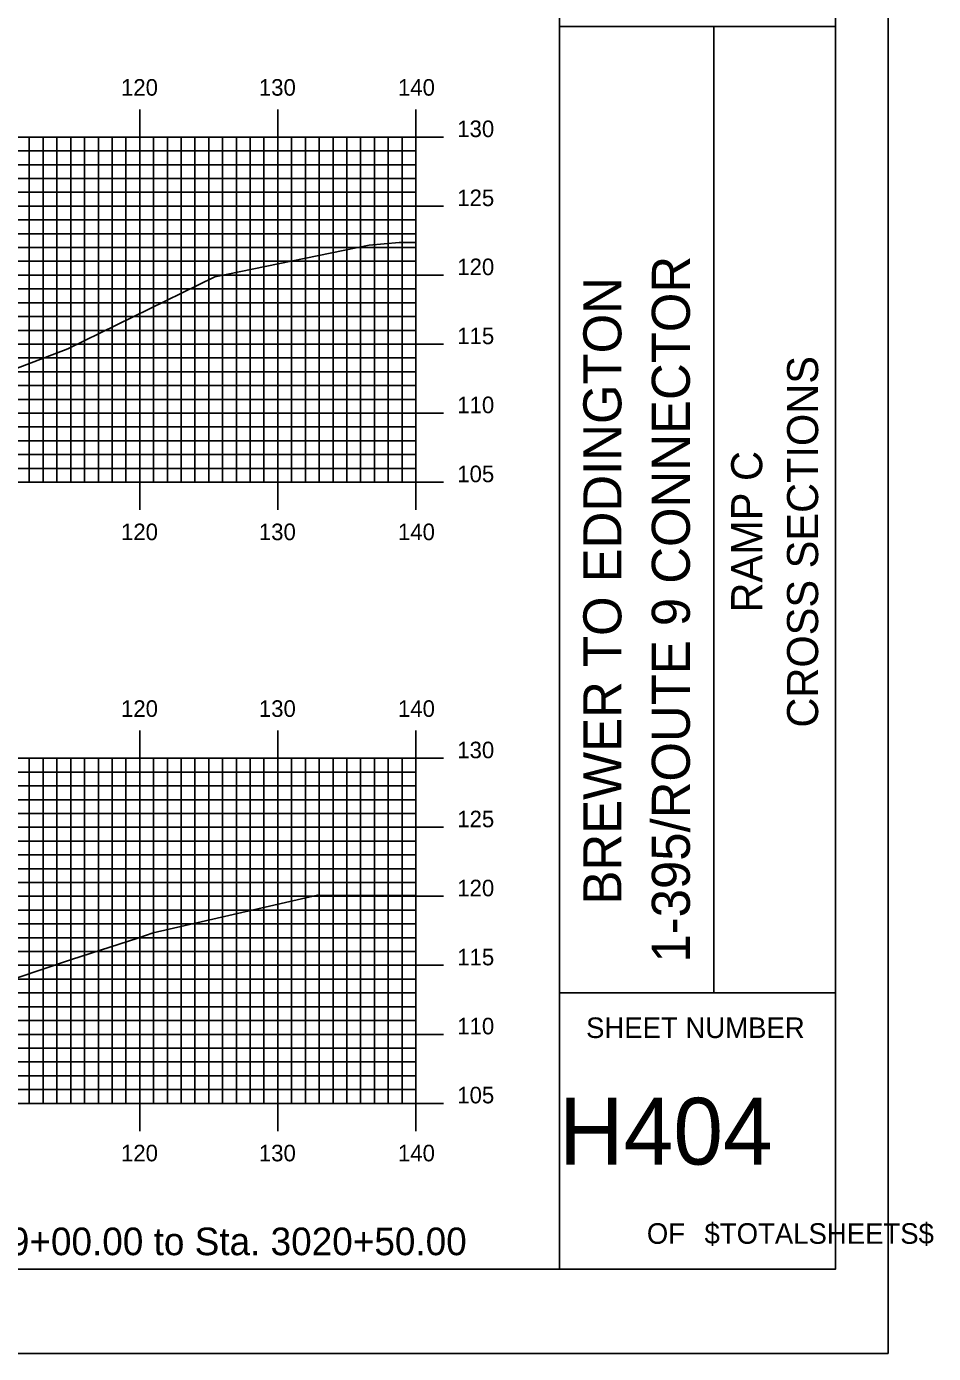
# Model space of a CAD drawing. Extents: x 1685979 to 1686323, y 461260 to 461480.
# Drawn here: x 1686257.1 to 1686322.8, y 461260 to 461356.1 of the extents above; entities that cross this region are included whole.
import ezdxf

# ---------------------------------------------------------------- set-up
doc = ezdxf.new("R2010")
doc.units = 0
for name, color, linetype in [('BORDER', 7, 'Continuous'), ('H_V ANNOTATION', 7, 'Continuous'), ('MAJOR', 7, 'Continuous'), ('MINOR', 7, 'Continuous'), ('PLOT BOUNDARY', 7, 'Continuous'), ('S_Roadway_Centerline', 7, 'Continuous')]:
    doc.layers.add(name, color=color, linetype=linetype)

msp = doc.modelspace()

# ---------------------------------------------------------------- linework, layer by layer
at = {"layer": 'BORDER'}
for p, q in [((1686295.656, 461266.072), (1686295.656, 461476.072)), ((1686295.656, 461356.078), (1686315.656, 461356.078)), ((1686306.838, 461286.078), (1686306.838, 461356.078)), ((1686295.656, 461286.078), (1686315.656, 461286.078))]:
    msp.add_line(p, q, dxfattribs=at)
msp.add_lwpolyline([(1685995.656, 461266.072), (1686315.656, 461266.072), (1686315.656, 461476.072), (1685995.656, 461476.072)], close=True, dxfattribs=at)
at = {"layer": 'MAJOR'}
for p, q in [((1686265.256, 461350.076), (1686265.256, 461348.072)), ((1686275.256, 461350.076), (1686275.256, 461348.072)), ((1686285.256, 461350.076), (1686285.256, 461348.072)), ((1686005.256, 461348.072), (1686285.256, 461348.072)), ((1686005.256, 461348.072), (1686285.256, 461348.072)), ((1686265.256, 461323.072), (1686265.256, 461348.072)), ((1686275.256, 461323.072), (1686275.256, 461348.072)), ((1686287.26, 461348.072), (1686283.252, 461348.072)), ((1686285.256, 461323.072), (1686285.256, 461348.072)), ((1686285.256, 461323.072), (1686285.256, 461348.072)), ((1686005.256, 461343.072), (1686285.256, 461343.072)), ((1686287.26, 461343.072), (1686283.252, 461343.072)), ((1686005.256, 461338.072), (1686285.256, 461338.072)), ((1686287.26, 461338.072), (1686283.252, 461338.072)), ((1686005.256, 461333.072), (1686285.256, 461333.072)), ((1686287.26, 461333.072), (1686283.252, 461333.072)), ((1686005.256, 461328.072), (1686285.256, 461328.072)), ((1686287.26, 461328.072), (1686283.252, 461328.072)), ((1686005.256, 461323.072), (1686285.256, 461323.072)), ((1686005.256, 461323.072), (1686285.256, 461323.072)), ((1686265.256, 461321.068), (1686265.256, 461323.072)), ((1686275.256, 461321.068), (1686275.256, 461323.072)), ((1686287.26, 461323.072), (1686283.252, 461323.072)), ((1686285.256, 461321.068), (1686285.256, 461323.072)), ((1686265.256, 461305.076), (1686265.256, 461303.072)), ((1686275.256, 461305.076), (1686275.256, 461303.072)), ((1686285.256, 461305.076), (1686285.256, 461303.072)), ((1686005.256, 461303.072), (1686285.256, 461303.072)), ((1686005.256, 461303.072), (1686285.256, 461303.072)), ((1686265.256, 461278.072), (1686265.256, 461303.072)), ((1686275.256, 461278.072), (1686275.256, 461303.072)), ((1686287.26, 461303.072), (1686283.252, 461303.072)), ((1686285.256, 461278.072), (1686285.256, 461303.072)), ((1686285.256, 461278.072), (1686285.256, 461303.072)), ((1686005.256, 461298.072), (1686285.256, 461298.072)), ((1686287.26, 461298.072), (1686283.252, 461298.072)), ((1686005.256, 461293.072), (1686285.256, 461293.072)), ((1686287.26, 461293.072), (1686283.252, 461293.072)), ((1686005.256, 461288.072), (1686285.256, 461288.072)), ((1686287.26, 461288.072), (1686283.252, 461288.072)), ((1686005.256, 461283.072), (1686285.256, 461283.072)), ((1686287.26, 461283.072), (1686283.252, 461283.072)), ((1686005.256, 461278.072), (1686285.256, 461278.072)), ((1686005.256, 461278.072), (1686285.256, 461278.072)), ((1686265.256, 461276.068), (1686265.256, 461278.072)), ((1686275.256, 461276.068), (1686275.256, 461278.072)), ((1686287.26, 461278.072), (1686283.252, 461278.072)), ((1686285.256, 461276.068), (1686285.256, 461278.072))]:
    msp.add_line(p, q, dxfattribs=at)
at = {"layer": 'MINOR'}
for p, q in [((1686257.256, 461323.072), (1686257.256, 461348.072)), ((1686258.256, 461323.072), (1686258.256, 461348.072)), ((1686259.256, 461323.072), (1686259.256, 461348.072)), ((1686260.256, 461323.072), (1686260.256, 461348.072)), ((1686261.256, 461323.072), (1686261.256, 461348.072)), ((1686262.256, 461323.072), (1686262.256, 461348.072)), ((1686263.256, 461323.072), (1686263.256, 461348.072)), ((1686264.256, 461323.072), (1686264.256, 461348.072)), ((1686266.256, 461323.072), (1686266.256, 461348.072)), ((1686267.256, 461323.072), (1686267.256, 461348.072)), ((1686268.256, 461323.072), (1686268.256, 461348.072)), ((1686269.256, 461323.072), (1686269.256, 461348.072)), ((1686270.256, 461323.072), (1686270.256, 461348.072)), ((1686271.256, 461323.072), (1686271.256, 461348.072)), ((1686272.256, 461323.072), (1686272.256, 461348.072)), ((1686273.256, 461323.072), (1686273.256, 461348.072)), ((1686274.256, 461323.072), (1686274.256, 461348.072)), ((1686276.256, 461323.072), (1686276.256, 461348.072)), ((1686277.256, 461323.072), (1686277.256, 461348.072)), ((1686278.256, 461323.072), (1686278.256, 461348.072)), ((1686279.256, 461323.072), (1686279.256, 461348.072)), ((1686280.256, 461323.072), (1686280.256, 461348.072)), ((1686281.256, 461323.072), (1686281.256, 461348.072)), ((1686282.256, 461323.072), (1686282.256, 461348.072)), ((1686283.256, 461323.072), (1686283.256, 461348.072)), ((1686284.256, 461323.072), (1686284.256, 461348.072)), ((1686005.256, 461347.072), (1686285.256, 461347.072)), ((1686285.256, 461347.072), (1686283.252, 461347.072)), ((1686005.256, 461346.072), (1686285.256, 461346.072)), ((1686285.256, 461346.072), (1686283.252, 461346.072)), ((1686005.256, 461345.072), (1686285.256, 461345.072)), ((1686285.256, 461345.072), (1686283.252, 461345.072)), ((1686005.256, 461344.072), (1686285.256, 461344.072)), ((1686285.256, 461344.072), (1686283.252, 461344.072)), ((1686005.256, 461342.072), (1686285.256, 461342.072)), ((1686285.256, 461342.072), (1686283.252, 461342.072)), ((1686005.256, 461341.072), (1686285.256, 461341.072)), ((1686285.256, 461341.072), (1686283.252, 461341.072)), ((1686005.256, 461340.072), (1686285.256, 461340.072)), ((1686285.256, 461340.072), (1686283.252, 461340.072)), ((1686005.256, 461339.072), (1686285.256, 461339.072)), ((1686285.256, 461339.072), (1686283.252, 461339.072)), ((1686005.256, 461337.072), (1686285.256, 461337.072)), ((1686285.256, 461337.072), (1686283.252, 461337.072)), ((1686005.256, 461336.072), (1686285.256, 461336.072)), ((1686285.256, 461336.072), (1686283.252, 461336.072)), ((1686005.256, 461335.072), (1686285.256, 461335.072)), ((1686285.256, 461335.072), (1686283.252, 461335.072)), ((1686005.256, 461334.072), (1686285.256, 461334.072)), ((1686285.256, 461334.072), (1686283.252, 461334.072)), ((1686005.256, 461332.072), (1686285.256, 461332.072)), ((1686285.256, 461332.072), (1686283.252, 461332.072)), ((1686005.256, 461331.072), (1686285.256, 461331.072)), ((1686285.256, 461331.072), (1686283.252, 461331.072)), ((1686005.256, 461330.072), (1686285.256, 461330.072)), ((1686285.256, 461330.072), (1686283.252, 461330.072)), ((1686005.256, 461329.072), (1686285.256, 461329.072)), ((1686285.256, 461329.072), (1686283.252, 461329.072)), ((1686005.256, 461327.072), (1686285.256, 461327.072)), ((1686285.256, 461327.072), (1686283.252, 461327.072)), ((1686005.256, 461326.072), (1686285.256, 461326.072)), ((1686285.256, 461326.072), (1686283.252, 461326.072)), ((1686005.256, 461325.072), (1686285.256, 461325.072)), ((1686285.256, 461325.072), (1686283.252, 461325.072)), ((1686005.256, 461324.072), (1686285.256, 461324.072)), ((1686285.256, 461324.072), (1686283.252, 461324.072)), ((1686257.256, 461278.072), (1686257.256, 461303.072)), ((1686258.256, 461278.072), (1686258.256, 461303.072)), ((1686259.256, 461278.072), (1686259.256, 461303.072)), ((1686260.256, 461278.072), (1686260.256, 461303.072)), ((1686261.256, 461278.072), (1686261.256, 461303.072)), ((1686262.256, 461278.072), (1686262.256, 461303.072)), ((1686263.256, 461278.072), (1686263.256, 461303.072)), ((1686264.256, 461278.072), (1686264.256, 461303.072)), ((1686266.256, 461278.072), (1686266.256, 461303.072)), ((1686267.256, 461278.072), (1686267.256, 461303.072)), ((1686268.256, 461278.072), (1686268.256, 461303.072)), ((1686269.256, 461278.072), (1686269.256, 461303.072)), ((1686270.256, 461278.072), (1686270.256, 461303.072)), ((1686271.256, 461278.072), (1686271.256, 461303.072)), ((1686272.256, 461278.072), (1686272.256, 461303.072)), ((1686273.256, 461278.072), (1686273.256, 461303.072)), ((1686274.256, 461278.072), (1686274.256, 461303.072)), ((1686276.256, 461278.072), (1686276.256, 461303.072)), ((1686277.256, 461278.072), (1686277.256, 461303.072)), ((1686278.256, 461278.072), (1686278.256, 461303.072)), ((1686279.256, 461278.072), (1686279.256, 461303.072)), ((1686280.256, 461278.072), (1686280.256, 461303.072)), ((1686281.256, 461278.072), (1686281.256, 461303.072)), ((1686282.256, 461278.072), (1686282.256, 461303.072)), ((1686283.256, 461278.072), (1686283.256, 461303.072)), ((1686284.256, 461278.072), (1686284.256, 461303.072)), ((1686005.256, 461302.072), (1686285.256, 461302.072)), ((1686285.256, 461302.072), (1686283.252, 461302.072)), ((1686005.256, 461301.072), (1686285.256, 461301.072)), ((1686285.256, 461301.072), (1686283.252, 461301.072)), ((1686005.256, 461300.072), (1686285.256, 461300.072)), ((1686285.256, 461300.072), (1686283.252, 461300.072)), ((1686005.256, 461299.072), (1686285.256, 461299.072)), ((1686285.256, 461299.072), (1686283.252, 461299.072)), ((1686005.256, 461297.072), (1686285.256, 461297.072)), ((1686285.256, 461297.072), (1686283.252, 461297.072)), ((1686005.256, 461296.072), (1686285.256, 461296.072)), ((1686285.256, 461296.072), (1686283.252, 461296.072)), ((1686005.256, 461295.072), (1686285.256, 461295.072)), ((1686285.256, 461295.072), (1686283.252, 461295.072)), ((1686005.256, 461294.072), (1686285.256, 461294.072)), ((1686285.256, 461294.072), (1686283.252, 461294.072)), ((1686005.256, 461292.072), (1686285.256, 461292.072)), ((1686285.256, 461292.072), (1686283.252, 461292.072)), ((1686005.256, 461291.072), (1686285.256, 461291.072)), ((1686285.256, 461291.072), (1686283.252, 461291.072)), ((1686005.256, 461290.072), (1686285.256, 461290.072)), ((1686285.256, 461290.072), (1686283.252, 461290.072)), ((1686005.256, 461289.072), (1686285.256, 461289.072)), ((1686285.256, 461289.072), (1686283.252, 461289.072)), ((1686005.256, 461287.072), (1686285.256, 461287.072)), ((1686285.256, 461287.072), (1686283.252, 461287.072)), ((1686005.256, 461286.072), (1686285.256, 461286.072)), ((1686285.256, 461286.072), (1686283.252, 461286.072)), ((1686005.256, 461285.072), (1686285.256, 461285.072)), ((1686285.256, 461285.072), (1686283.252, 461285.072)), ((1686005.256, 461284.072), (1686285.256, 461284.072)), ((1686285.256, 461284.072), (1686283.252, 461284.072)), ((1686005.256, 461282.072), (1686285.256, 461282.072)), ((1686285.256, 461282.072), (1686283.252, 461282.072)), ((1686005.256, 461281.072), (1686285.256, 461281.072)), ((1686285.256, 461281.072), (1686283.252, 461281.072)), ((1686005.256, 461280.072), (1686285.256, 461280.072)), ((1686285.256, 461280.072), (1686283.252, 461280.072)), ((1686005.256, 461279.072), (1686285.256, 461279.072)), ((1686285.256, 461279.072), (1686283.252, 461279.072))]:
    msp.add_line(p, q, dxfattribs=at)
at = {"layer": 'PLOT BOUNDARY'}
msp.add_lwpolyline([(1685979.469, 461259.954), (1686319.469, 461259.954), (1686319.469, 461479.954), (1685979.469, 461479.954)], close=True, dxfattribs=at)
at = {"layer": 'S_Roadway_Centerline'}
for points in [[(1686255.431, 461330.978), (1686260.041, 461332.736), (1686270.704, 461337.937), (1686281.879, 461340.242), (1686284.04, 461340.448), (1686285.256, 461340.446)], [(1686250.337, 461285.142), (1686260.318, 461288.499), (1686263.765, 461289.593), (1686265.108, 461290.04), (1686266.238, 461290.423), (1686278.126, 461293.159), (1686285.256, 461293.126)]]:
    msp.add_lwpolyline(points, dxfattribs=at)

# ---------------------------------------------------------------- texts
at = {"layer": 'BORDER'}
for s, height, p in [('1-395/ROUTE 9 CONNECTOR', 2.75575, (1686305.105, 461288.272)), ('BREWER TO EDDINGTON', 2.75575, (1686300.144, 461292.481)), ('CROSS SECTIONS', 2.25, (1686314.397, 461305.294)), ('RAMP C', 2.25, (1686310.347, 461313.629))]:
    msp.add_text(s, height=height, rotation=90, dxfattribs=at).set_placement(p)
for s, height, p in [('SHEET NUMBER', 1.49054, (1686297.586, 461282.805)), ('H404', 4.8388, (1686295.637, 461273.637)), ('OF', 1.4905, (1686301.989, 461267.898)), ('$TOTALSHEETS$', 1.49054, (1686306.169, 461267.898))]:
    msp.add_text(s, height=height, dxfattribs=at).set_placement(p)
at = {"layer": 'H_V ANNOTATION'}
for s, height, p in [('120', 1.2, (1686263.896, 461351.072)), ('130', 1.2, (1686273.885, 461351.072)), ('140', 1.2, (1686283.96, 461351.072)), ('130', 1.2, (1686288.256, 461348.072)), ('125', 1.2, (1686288.256, 461343.072)), ('120', 1.2, (1686288.256, 461338.072)), ('115', 1.2, (1686288.256, 461333.072)), ('110', 1.2, (1686288.256, 461328.072)), ('105', 1.2, (1686288.256, 461323.072)), ('120', 1.2, (1686263.896, 461318.872)), ('130', 1.2, (1686273.885, 461318.872)), ('140', 1.2, (1686283.96, 461318.872)), ('120', 1.2, (1686263.896, 461306.072)), ('130', 1.2, (1686273.885, 461306.072)), ('140', 1.2, (1686283.96, 461306.072)), ('130', 1.2, (1686288.256, 461303.072)), ('125', 1.2, (1686288.256, 461298.072)), ('120', 1.2, (1686288.256, 461293.072)), ('115', 1.2, (1686288.256, 461288.072)), ('110', 1.2, (1686288.256, 461283.072)), ('105', 1.2, (1686288.256, 461278.072)), ('120', 1.2, (1686263.896, 461273.872)), ('130', 1.2, (1686273.885, 461273.872)), ('140', 1.2, (1686283.96, 461273.872)), ('Sta. 3019+00.00 to Sta. 3020+50.00', 2.0004, (1686245.808, 461267.072))]:
    msp.add_text(s, height=height, dxfattribs=at).set_placement(p)

doc.saveas('drawing.dxf')
